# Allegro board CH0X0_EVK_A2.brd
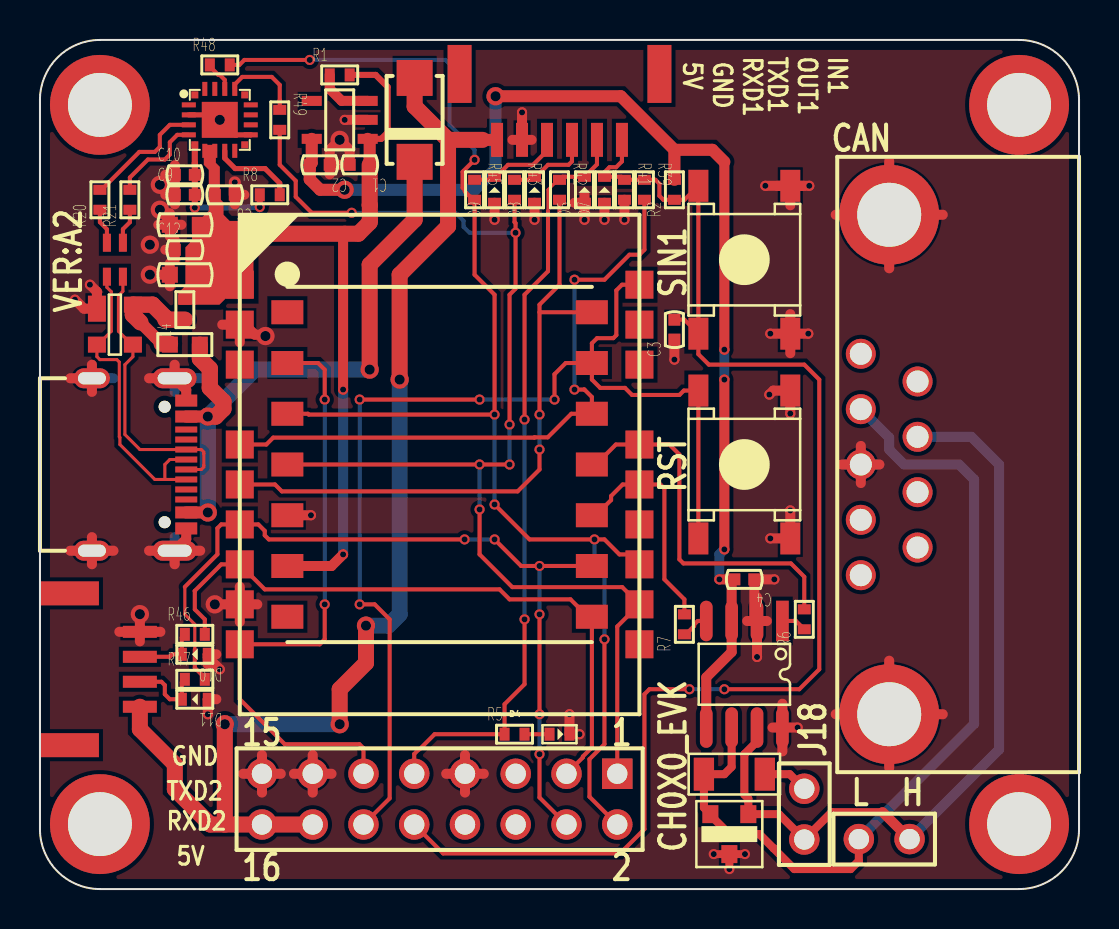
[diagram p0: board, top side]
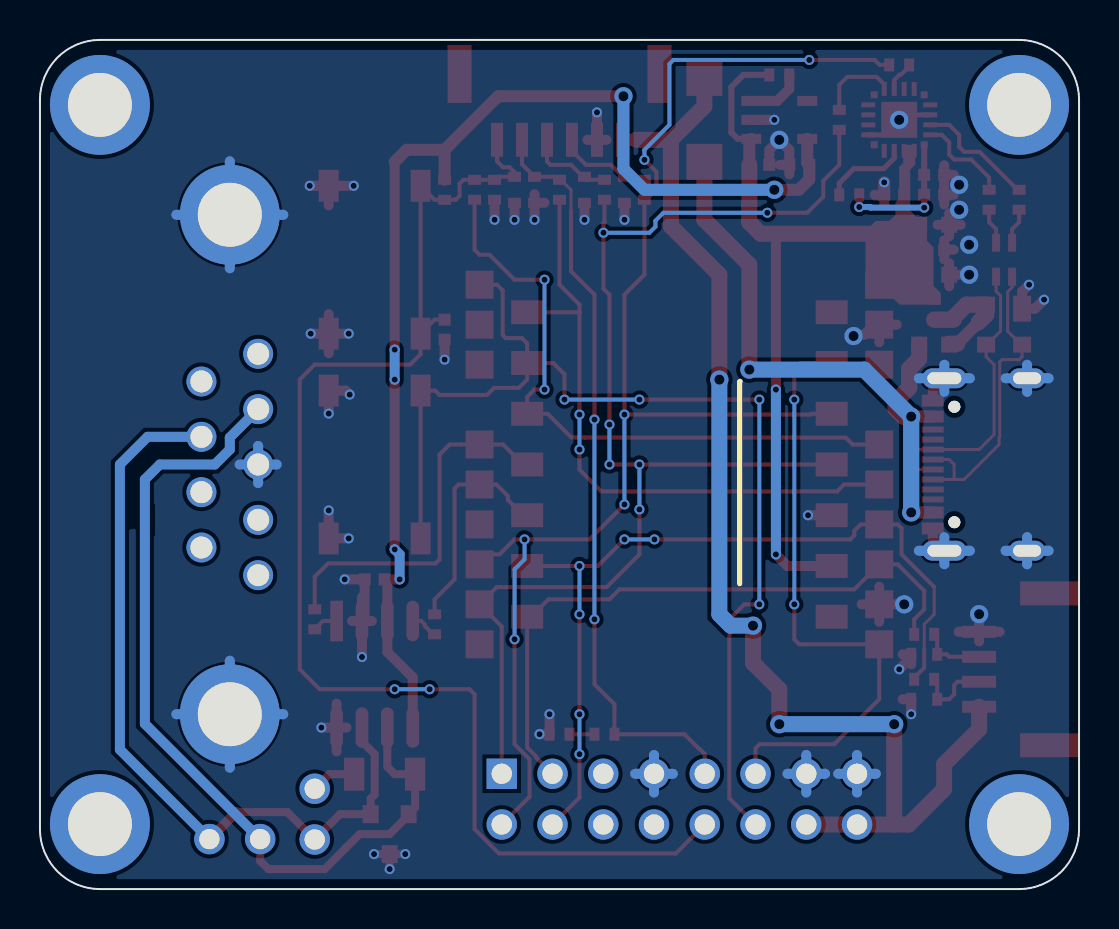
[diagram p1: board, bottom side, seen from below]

Outline 52 x 42.5 mm; copper layers: TOP, BOTTOM. Coordinates in mm from the lower left corner of the outline.
Outline path: 0,39.5 0,3 arc(0.88,0.88) 3,0 49,0 arc(51.12,0.88) 52,3 52,39.5 arc(51.12,41.62) 49,42.5 3,42.5 arc(0.88,41.62) 0,39.5

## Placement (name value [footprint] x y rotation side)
C1  0.1uF  [C0402]  16 36.25 180 top
C2  1uF  [C0402]  14 36.25 180 top
C3  0.1uF  [C0402]  31.75 28 90 top
C4  0.1uF  [C0402]  35.25 15.5 180 top
C7  10uF  [C0603]  7.25 33.25 0 top
C8  0.1uF  [C0402]  9.25 34.75 180 top
C9  0.1uF  [C0402]  7.25 34.75 0 top
C10  1uF  [C0402]  7.25 35.75 0 top
C11  10uF  [C0603]  7.25 30.75 0 top
C12  0.1uF  [C0402]  7.25 32 0 top
D1  1N4007  [DO-214AC]  18.75 38.5 90 top
D3  SM24CANB-02HTG  [SOT23-3-0_95]  34.5 2.75 180 top
D4  RED  [LED0402]  26 7.75 0 top
D6  SBD52C05L01  [SOD-523]  27.25 35 90 top
D7  SBD52C05L01  [SOD-523]  28.25 35 90 top
D8  SBD52C05L01  [SOD-523]  24.75 35 90 top
D9  SBD52C05L01  [SOD-523]  22.75 35 90 top
D10  SBD52C05L01  [SOD-523]  7.75 11.75 180 top
D11  SBD52C05L01  [SOD-523]  7.75 9.5 180 top
DN1  UET14A05L03  [SOT143]  3.75 28.25 270 top
F2  300mA  [F0603]  7.25 27.25 180 top
H1  HOLE  [HOLE-3-MM]  3 39.25 0 top
H2  HOLE  [HOLE-3-MM]  3 3.25 0 top
H3  HOLE  [HOLE-3-MM]  49 3.25 0 top
H4  HOLE  [HOLE-3-MM]  49 39.25 0 top
J1  CON6  [A1257WV-S-6P]  26 37.5 0 top
J2  CON4  [GH1X4-1_25MM_90]  5 11 90 top
J3  CONN PCB 8x2  [HEADER2X8-2_54MM]  20 4.5 180 top
J5  DB9  [DB9_FEMALE]  42.5 21.25 270 top
J6  CONN PCB 2  [HEADER1X2-2_54MM]  42.25 2.5 180 top
J7  TYPEC-311SDS-ACP16  [TYPE_C_U262_161N]  0 21.25 270 top
J18  CON2  [HEADER1X2-2_54MM]  38.25 3.75 90 top
K1  Button2  [BUTTON_6X6]  35.25 21.25 0 top
K2  Button2  [BUTTON_6X6]  35.25 31.5 0 top
L4  FB  [L0402]  7.25 29 90 top
NOREF  -  []  51.17 41.57 0 top
NOREF#2  -  []  52 3 90 top
NOREF#3  -  []  3 42.5 0 top
R1  4.7K  [R0402]  15 40.75 0 top
R2  4.7K  [R0402]  31.75 35 90 top
R3  120R  [R1206]  34.75 5.75 180 top
R5  510R  [R0402]  23.75 7.75 0 top
R6  1K  [R0402]  38.25 13.5 90 top
R7  1K  [R0402]  32.25 13.25 90 top
R8  1K  [R0402]  11.5 34.75 0 top
R20  10R  [R0402]  3 34.5 90 top
R21  10R  [R0402]  4.5 34.5 90 top
R39  120R  [R0402]  30.25 35 270 top
R41  10K  [R0402]  29.25 35 270 top
R42  120R  [R0402]  26 35 270 top
R43  120R  [R0402]  23.75 35 270 top
R45  120R  [R0402]  21.75 35 270 top
R46  120R  [R0402]  7.75 12.75 0 top
R47  120R  [R0402]  7.75 10.5 0 top
R48  1K  [R0402]  9 41.25 0 top
R49  1K  [R0402]  12 38.5 270 top
T1  YLM2012-900T  [SMD2012_4P]  3.75 31.5 90 top
U1  RS3219-3.3YF5  [SOT23-5-0_95]  15 38.5 90 top
U2  SIT65HVD234DR  [SOP8]  35.25 10.75 270 top
U3  CH040  [CH100_MINI]  20 21.25 0 top
U4  CH020  [CH010]  20 21.25 0 top
U10  CP2012N  [QFN-20-3X3-P0_5-CP2102N]  9 38.5 0 top

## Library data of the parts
C1-C4 C7-C12 = Capacity_Nonpolarity
D1 = diode
D3 = BAT54A/SOT
D4 = LED
D6-D11 = DIODE BI-DIR TRIG
DN1 = DS_T_CA_1
F2 = Fuse
H1-H4 = HOLE
J1 = CON6
J2 = CON4
J3 = CONN PCB 8x2
J5 = CONN_DB9M_MTGTABS
J6 = CONN PCB 2
J7 = TYPE C 12P
J18 = CON2
K1 K2 = Button2
L4 = FB
R1-R3 R5-R8 R20 R21 R39 R41-R43 R45-R49 = Res
T1 = TRNSFMR 67125450
U1 = XC6210
U2 = SN65HVD234-Q1
U3 = CH100
U4 = CH020
U10 = CP2102N-A02-GQFN20

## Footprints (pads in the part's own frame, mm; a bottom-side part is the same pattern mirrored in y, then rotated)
A1257WV-S-6P
  rect 1.2x2.9 smd: (-5,3.3) (5,3.3)
  rect 0.6x1.7 smd: 1(-3.125,0) 2(-1.875,0) 3(-0.625,0) 4(0.625,0) 5(1.875,0) 6(3.125,0)
BUTTON_6X6
  rect 1x1.6 smd: 1(2.3,3.7) 2(2.3,-3.7) 3(-2.3,-3.7) 4(-2.3,3.7)
C0402
  rect 0.6x0.6 smd: 1(-0.5,0) 2(0.5,0)
C0603
  rect 0.8x0.8 smd: 1(-0.75,0) 2(0.75,0)
CH010
  rect 1.6x1.2 smd: 1(-7.62,7.62) 2(-7.62,5.08) 3(-7.62,2.54) 4(-7.62,0) 5(-7.62,-2.54) 6(-7.62,-5.08) 7(-7.62,-7.62) 8(7.62,-7.62) 9(7.62,-5.08) 10(7.62,-2.54) 11(7.62,0) 12(7.62,2.54) 13(7.62,5.08) 14(7.62,7.62)
CH100_MINI
  rect 1.4x1.4 smd: 1(-10,9) 2(-10,7) 3(-10,5) 4(-10,1) 5(-10,-1) 6(-10,-3) 7(-10,-5) 8(-10,-7) 9(-10,-9) 10(10,-9) 11(10,-7) 12(10,-5) 13(10,-3) 14(10,-1) 15(10,1) 16(10,5) 17(10,7) 18(10,9)
DB9_FEMALE
  round 1.5 hole 1.1: 1(-5.54,-1.42) 2(-2.77,-1.42) 3(0,-1.42) 4(2.77,-1.42) 5(5.54,-1.42) 6(-4.155,1.42) 7(-1.385,1.42) 8(1.385,1.42) 9(4.155,1.42)
  round 5 hole 3.2: M1(12.5,0) M2(-12.5,0)
DO-214AC
  rect 1.8x1.8 smd: 1(2.1,0) 2(-2.1,0)
F0603
  rect 0.8x0.8 smd: 1(-0.75,0) 2(0.75,0)
GH1X4-1_25MM_90
  rect 1.2x2.9 smd: (-3.8,3.5) (3.8,3.5)
  rect 0.6x1.7 smd: 1(-1.875,0) 2(-0.625,0) 3(0.625,0) 4(1.875,0)
HEADER1X2-2_54MM
  round 1.524 hole 1.016: 1(-1.27,0) 2(1.27,0)
HEADER2X8-2_54MM
  rect 1.524x1.524 hole 1.016: 1(-8.89,-1.27)
  round 1.524 hole 1.016: 2(-8.89,1.27) 3(-6.35,-1.27) 4(-6.35,1.27) 5(-3.81,-1.27) 6(-3.81,1.27) 7(-1.27,-1.27) 8(-1.27,1.27) 9(1.27,-1.27) 10(1.27,1.27) 11(3.81,-1.27) 12(3.81,1.27) 13(6.35,-1.27) 14(6.35,1.27) 15(8.89,-1.27) 16(8.89,1.27)
HOLE-3-MM
  round 5 hole 3.2: 1(0,0)
L0402
  rect 0.5x0.65 smd: 1(-0.5,0) 2(0.5,0)
LED0402
  rect 0.5x0.65 smd: 1(-0.5,0) 2(0.5,0)
QFN-20-3X3-P0_5-CP2102N
  rect 0.35x0.35 smd: 1(-1.25,1.25) 6(-1.25,-1.25) 11(1.25,-1.25) 16(1.25,1.25)
  rect 0.7x0.25 smd: 2(-1.55,0.75) 3(-1.55,0.25) 4(-1.55,-0.25) 5(-1.55,-0.75) 12(1.55,-0.75) 13(1.55,-0.25) 14(1.55,0.25) 15(1.55,0.75)
  rect 0.25x0.7 smd: 7(-0.75,-1.55) 8(-0.25,-1.55) 9(0.25,-1.55) 10(0.75,-1.55) 17(0.75,1.55) 18(0.25,1.55) 19(-0.25,1.55) 20(-0.75,1.55)
  rect 1.8x1.8 smd: 21(0,0)
R0402
  rect 0.5x0.65 smd: 1(-0.5,0) 2(0.5,0)
R1206
  rect 1.016x1.651 smd: 1(-1.524,0) 2(1.524,0)
SMD2012_4P
  rect 0.9x0.4 smd: 1(-0.85,0.4) 2(0.85,0.4) 3(-0.85,-0.4) 4(0.85,-0.4)
SOD-523
  rect 0.5x0.65 smd: 1(-0.65,0) 2(0.65,0)
SOP8
  rect 2.032x0.635 smd: 1(-2.667,1.905)
  oval 2.032x0.635 smd: 2(-2.667,0.635) 3(-2.667,-0.635) 4(-2.667,-1.905) 5(2.667,-1.905) 6(2.667,-0.635) 7(2.667,0.635) 8(2.667,1.905)
SOT23-3-0_95
  rect 0.8x0.9 smd: 1(-0.95,-1) 2(0.95,-1) 3(0,1)
SOT23-5-0_95
  rect 0.5x1 smd: 1(-0.95,-1.4) 2(0,-1.4) 3(0.95,-1.4) 4(0.95,1.4) 5(-0.95,1.4)
SOT143
  rect 1.3x0.9 smd: 1(-0.8,-0.9)
  rect 0.8x0.9 smd: 2(1,-0.9) 3(1,0.9) 4(-1,0.9)
TYPE_C_U262_161N
  round 0.6 hole 0.6 unplated: (-2.89,6.24) (2.89,6.24)
  oval 1x1.8 hole 0.6x1.4: 13(4.315,2.6) 16(-4.315,2.6)
  oval 1x2.2 hole 0.6x1.7: 14(-4.315,6.74) 15(4.315,6.74)
  rect 0.6x1.1 smd: A1B12(-3.2,7.32) A4B9(-2.4,7.32) B1A12(3.2,7.32) B4A9(2.4,7.32)
  rect 0.3x1.1 smd: A5(-1.25,7.32) A6(-0.25,7.32) A7(0.25,7.32) A8(1.25,7.32) B5(1.75,7.32) B6(0.75,7.32) B7(-0.75,7.32) B8(-1.75,7.32)

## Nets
GND: C1.2 C2.1 C3.1 C4.1 C7.1 C8.1 C9.1 C10.1 C11.1 C12.1 D3.3 D4.2(-) D6.1 D7.1 D8.1 D9.1 D10.1 D11.1 DN1.1 J1.2 J2.4 J3.7(12) J3.13(15) J3.15(16) J5.3 J5.M1 J5.M2 J7.13(S1) J7.14(S2) J7.15(S3) J7.16(S4) J7.A1B12(GND#A1B12) J7.B1A12(GND#B1A12) K1.1 K1.2 K2.1 K2.2 R41.2 U1.2(VSS) U2.2(GND) U2.8(RS) U3.2(GND#2) U3.8(GND#8) U4.5(GND) U10.3(GND#3) U10.12(GND#12) U10.21(GND#21)
VBUS: D1.2(N) F2.1 J7.A4B9(VBUS#A4B9) J7.B4A9(VBUS#B4A9)
VCC: DN1.4 F2.2 L4.1
CAN_RX: R7.2 U3.14(CAN_RX) U4.10(CAN_RX)
CAN_TX: R6.2 U3.15(CAN_TX) U4.11(CAN_TX)
CANH: D3.1 J5.7 J6.1 J18.1 U2.7(CAN-H)
CANL: D3.2 J5.2 J6.2 R3.2 U2.6(CAN-L)
CC2: J7.B5(CC2)
CP2104_RXD: R49.1 U10.17(RXD)
CP2104_TXD: R48.1 U10.18(TXD)
DP3V3: C2.2 C4.2 R2.2 U1.5(VOUT) U2.3(VCC) U2.5(EN)
DP5V: C1.1 C7.2 C8.2 C11.2 C12.2 L4.2 R1.2 U1.1(VIN) U3.1(VCC) U4.6(VCC) U10.7(VREGIN) U10.8(VBUS)
EN: U3.3(EN)
IO5: J3.11(14) U3.9(IO5) U4.2(IO5)
NRST: J3.12(6) K1.3 K1.4 U3.18(NRST) U4.13(NRST)
POWER: D1.1(P) J1.1 J2.1 J3.14(7) J3.16(8)
RXD1: J3.2(1) R45.2 R48.2 U3.12(RXD1) U4.3(RXD1)
RXD2: J3.4(2) R47.2 U3.6(RXD2) U4.9(RXD2)
RXD_1: D9.2 J1.3 R45.1
RXD_2: D11.2 J2.2 R47.1
SIN: C3.2 D7.2 J1.6 J3.10(5) K2.3 K2.4 R2.1 R39.1 R41.1
SOUT: D6.2 J1.5 J3.9(13) R5.1 R42.1
SYNC_IN: R39.2 U3.4(SYNC_IN) U4.12(SYNC_IN)
SYNC_OUT: R42.2 U3.5(SYNC_OUT) U4.14(SYNC_OUT)
TXD1: J3.1(9) R43.2 R49.2 U3.11(TXD1) U4.4(TXD1)
TXD2: J3.3(10) R46.2 U3.7(TXD2) U4.8(TXD2)
TXD_1: D8.2 J1.4 R43.1
TXD_2: D10.2 J2.3 R46.1
USB_DN: DN1.3 J7.A7(DN1) J7.B7(DN2) T1.3(OUT1)
USB_DP: DN1.2 J7.A6(DP1) J7.B6(DP2) T1.1(IN1)
N1746824: D4.1(+) R5.2
N1748528: R1.1 U1.3(CE)
N1750382: R7.1 U2.4(RXD)
N1750594: R6.1 U2.1(TXD)
N1756014: C9.2 C10.2 R8.1 U10.6(VDD)
N1756148: R8.2 U10.9(RSTB)
N1756188: R20.1 T1.2(IN2)
N1756192: R21.1 T1.4(OUT2)
N1756238: R21.2 U10.5(D-)
N1756242: R20.2 U10.4(D+)
N1912221: J18.2 R3.1

Pads without a net: H1 1; H2 1; H3 1; H4 1; J3 5 6 8; J5 1 4 5 6 8 9; J7 A5 A8 B8; U1 4; U3 10 13 16 17; U4 1 7; U10 1 2 10 11 13 14 15 16 19 20

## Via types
v1: diameter 0.914, hole 0.508, TOP to BOTTOM, 18 vias
v2: diameter 0.508, hole 0.305, TOP to BOTTOM, 70 vias

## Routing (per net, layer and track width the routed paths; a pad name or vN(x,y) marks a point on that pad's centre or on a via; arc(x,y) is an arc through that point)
GND: length 174.3
  TOP w0.254: U10.3 8.75,38.75 v1(9,38.5) 9.75,37.75 U10.12
  TOP w0.4: D3.3 v2(33.72,1.75) ; D3.3 v2(34.5,1) ; D3.3 v2(35.28,1.75)
  TOP w0.5: D11.1 v2(8.4,8.75) ; D11.1 8.83,9.5 ; D11.1 8.4,9 ; J5.M2 45.18,33.75 ; J5.M2 42.5,31.07 ; J5.M2 42.5,36.43 ; J5.M2 39.82,33.75 ; 6.5,32.67 C7.1 ; C7.1 7.08,33.25 ; C7.1 5.92,33.25 ; C7.1 6.5,33.83 ; C1.2 15.5,37 v1(15,37.5) 14.5,37 C2.1 ; 42.5,6.07 J5.M1 ; J5.M1 39.82,8.75 ; J5.M1 45.18,8.75 ; J5.M1 42.5,11.43 ; J1.2 v2(24.12,38.88) ; J1.2 23.65,37.5 ; J1.2 24.6,37.5 ; 5.46,25.56 J7.14 ; J7.14 6.74,26.24 ; J7.14 7.32,24.98 J7.A1B12 ; J3.13 13.65,6.71 ; J3.13 12.71,5.77 ; J3.13 13.65,4.83 ; J3.13 14.59,5.77 ; C10.1 6.75,36.23 ; C10.1 6.27,35.75 ; C10.1 6.75,35.27 ; D8.1 v2(24.75,33.5) ; D6.1 27.25,34.78 ; D6.1 v2(27.25,33.5) ; D6.1 26.75,34.35 ; 20.33,5.77 J3.7 ; J3.7 21.27,4.83 ; J3.7 21.27,6.71 ; J3.7 22.21,5.77 ; 1.52,25.56 J7.16 ; J7.16 2.6,24.89 ; J7.16 2.6,26.24 ; 5.46,16.93 J7.15 ; J7.15 8.02,16.93 ; J7.15 7.32,17.52 J7.B1A12 ; J7.15 6.74,16.26 ; J2.4 v1(5,13.76) ; J2.4 3.97,12.88 ; J2.4 5,12.4 ; J2.4 6.03,12.88 ; J7.13 2.6,17.61 ; J7.13 3.68,16.93 ; J7.13 2.6,16.26 ; J7.13 1.52,16.93 ; D9.1 v2(22.75,33.5) ; J3.15 12.05,5.77 ; J3.15 11.11,6.71 ; J3.15 10.17,5.77 ; J3.15 11.11,4.83 ; C12.1 6.75,32.48 ; C12.1 6.75,31.52 ; C12.1 6.27,32 ; K2.1 v2(36.3,35.2) ; K2.1 37.55,34.22 ; K2.1 38.23,35.2 ; K2.1 v2(38.5,35.2) ; K2.1 36.87,35.2 ; D10.1 8.4,11.6 v2(9,11) ; D10.1 8.4,11.25 ; D10.1 8.83,11.75 ; v2(36.75,15.5) C4.1 35.75,13.55 U2.2 ; 41.08,20.32 J5.3 ; J5.3 42.01,21.25 ; J5.3 41.08,22.18 ; J5.3 40.15,21.25 ; 10,27.37 U3.2 ; U3.2 9.12,28.25 ; U3.2 10.25,28.25 10.75,27.75 11.21,27.75 v1(11.28,27.68) ; U2.2 36.38,13.42 ; U2.2 v2(35.88,11.61) ; U2.2 35.88,14.61 ; U2.2 35.39,13.42 ; U2.8 v2(37.92,8.08) ; U2.8 37.15,6.89 ; U2.8 36.66,8.08 ; U2.8 37.15,9.28 ; v2(37.55,23.8) K1.1 36.7,24.95 v2(36.5,24.75) ; 10.23,34.75 C8.1 9.75,34.27 ; 6.75,34.27 C9.1 ; C9.1 6.27,34.75 ; C9.1 6.75,35.23 ; U3.8 10,15.13 ; U3.8 v1(8.75,14.25) ; U3.8 10.88,14.25 ; U3.8 10,13.37 ; K2.2 37.55,28.78 ; K2.2 v2(36.55,27.8) ; K2.2 37.55,26.82 ; K2.2 v2(38.45,27.8) ; v2(27,7.75) D4.2 v2(26.5,8.75) ; v2(36.55,17.55) K1.2 v2(37.55,18.95) ; C2.1 14.5,35.77 ; C2.1 14.98,36.25 ; U4.5 v2(13.56,18.71) ; 5.92,30.75 C11.1 ; C11.1 6.5,30.17 ; C11.1 6.5,31.33 ; U1.2 v2(15.25,38.5) ; R41.2 v2(29.25,33.5) ; C3.1 v2(31.75,26.5) ; v2(1.75,29.5) 2.2,29.05 DN1.1 2.85,29.9 v2(2.5,30.25) ; D7.1 v2(28.25,33.5)
  TOP w0.6: C8.1 v2(9.75,35.37)
  BOTTOM w0.5: J3.15 12.05,5.77 ; J3.15 10.17,5.77 ; J3.15 11.11,6.71 ; J3.15 11.11,4.83 ; J5.M1 42.5,11.43 ; J5.M1 45.18,8.75 ; J5.M1 39.82,8.75 ; J5.M1 42.5,6.07 ; J5.M2 42.5,36.43 ; J5.M2 45.18,33.75 ; J5.M2 39.82,33.75 ; J5.M2 42.5,31.07 ; J7.16 3.68,25.56 ; J7.16 2.6,26.24 ; J7.16 1.52,25.56 ; J7.16 2.6,24.89 ; J3.7 21.27,6.71 ; J3.7 20.33,5.77 ; J3.7 21.27,4.83 ; J3.7 22.21,5.77 ; J7.15 6.74,17.61 ; J7.15 6.74,16.26 ; J7.15 8.02,16.93 ; J7.15 5.46,16.93 ; J7.14 6.74,26.24 ; J7.14 5.46,25.56 ; J7.14 6.74,24.89 ; J7.14 8.02,25.56 ; 12.71,5.77 J3.13 ; J3.13 14.59,5.77 ; J3.13 13.65,6.71 ; J3.13 13.65,4.83 ; 1.52,16.93 J7.13 ; J7.13 3.68,16.93 ; J7.13 2.6,16.26 ; J7.13 2.6,17.61 ; J5.3 42.01,21.25 ; J5.3 40.15,21.25 ; J5.3 41.08,20.32 ; J5.3 41.08,22.18
  vias: v1(5.5,32.25) v1(5.5,30.75) v1(6,35.25) v1(6,34)
VBUS: length 32
  TOP w0.6: 8,26.55 8,26.54 ; J7.A4B9 v1(8.4,23.65) ; J7.B4A9 v1(8.4,18.85)
  TOP w0.8: D1.2 18.75,33.5 16.5,31.25 v1(16.5,26) ; F2.1 8,26.55
  TOP w0.813: 8,26.54 8.5,26.05 8.5,25.08 9.18,24.41 9.18,24.04 8.79,23.65 v1(8.4,23.65)
  BOTTOM w0.8: v1(16.5,26) 10.75,26 v1(8.4,23.65)
  BOTTOM w0.813: v1(8.4,18.85) v1(8.4,23.65)
VCC: length 6.5
  TOP w0.6: F2.2 6.14,27.25 5.75,27.64 5.02,28.37 ; 6.28,28.5 6.38,28.5
  TOP w0.813: 5.02,28.37 4.65,28.74 DN1.4 5.63,29.25 6.28,28.61 ; 6.28,28.61 6.38,28.5 L4.1 ; 6.28,28.61 6.28,28.5 ; 6.5,27.3 6.09,27.3
CAN_RX: length 11.2
  TOP w0.203: R7.2 32.25,14.5 31.25,15.5 31.25,20.05 31.05,20.25 U3.14 29.16,20.25 28.58,19.67 28.58,19.47 27.82,18.71 U4.10
CAN_TX: length 18.5
  TOP w0.203: U4.11 27.82,21.25 28.82,22.25 U3.15 30.93,22.25 31.5,22.25 32,21.75 32,16.5 32.2,16.3 37.58,16.3 38.25,15.63 R6.2
CANH: length 39.7
  TOP w0.4: U2.7 35.88,7.38 35.25,6.75 35.25,4.73 35.45,4.53 D3.1 36.98,3.75 J18.1 39.62,3.85 42.17,3.85
  TOP w0.5: 42.17,3.85 J6.1
  BOTTOM w0.5: J6.1 48,6.98 48,21.25 46.61,22.64 J5.7
CANL: length 43.4
  TOP w0.4: J6.2 40.98,1.41 40.57,1 37.75,1 36.71,2.04 36.71,2.04 36,2.75 34.5,2.75 33.55,3.7 D3.2 33.23,4.07 R3.2 34.25,5.75 34.61,6.11 U2.6
  BOTTOM w0.5: J5.2 42.5,22.6 42.5,22 43.25,21.25 46,21.25 46.75,20.5 46.75,8.27 J6.2
CP2104_RXD: length 4
  TOP w0.203: R49.1 12,39.48 12,40.25 11.6,40.65 10.12,40.65 9.75,40.28 U10.17
CP2104_TXD: length 1.6
  TOP w0.203: R48.1 8.5,41.18 8.91,40.76 8.99,40.76 9.25,40.5 U10.18
DP3V3: length 60.4
  TOP w0.305: U2.5 33.34,7.38
  TOP w0.5: U2.5 33.34,10.6 34.61,11.87 U2.3 34.61,15.36 C4.2 v2(34,15.5) ; v2(34.25,27) 34.25,36.4 ; v2(34.25,17) v2(34.25,25.5)
  TOP w0.6: 31.75,37 29.07,39.68 v1(22.8,39.68) ; 31.75,37 R2.2 ; 31.75,37 33.65,37 34.25,36.4 ; v1(15.25,35) 14.02,35 13.5,35.52 C2.2 13.6,36.35 U1.5
  BOTTOM w0.5: v2(34,15.5) 34,16.75 v2(34.25,17) ; v2(34.25,25.5) v2(34.25,27)
  BOTTOM w0.6: v1(15.25,35) 21.75,35 22.8,36.05 v1(22.8,39.68)
DP5V: length 35.8
  TOP w0.305: U1.1 17.08,37.55 17.4,37.87 17.4,40.15 16.8,40.75 R1.2
  TOP w0.5: 15.25,32.8 15.17,32.72 v2(15.17,25) ; U4.6 14.59,16.17 v2(15.17,16.75)
  TOP w0.6: C1.1 16.5,37.45 U1.1
  TOP w0.8: 9.85,32.8 15.93,32.8 16.5,33.37 16.5,33.47 16.51,33.47 16.51,34.23 16.5,34.23 C1.1
  BOTTOM w0.5: v2(15.17,16.75) v2(15.17,25)
IO5: length 31.1
  TOP w0.203: v2(14.25,24.5) 14.25,26 13.92,26.33 U4.2 ; J3.11 16.19,7.05 15.99,7.25 12.25,7.25 10,9.5 U3.9 14,12.25 14.25,12.5 v2(14.25,14.25)
  BOTTOM w0.203: v2(14.25,14.25) v2(14.25,24.5)
NRST: length 55.9
  TOP w0.203: v2(22,24.5) v2(16,24.5) ; K1.3 K1.4 32.22,24.95 32,24.73 29.63,24.73 29.28,25.09 28.04,25.09 27.62,25.5 U4.13 ; U4.13 27.62,27.32 27.88,27.57 28.69,27.57 28.84,27.73 28.84,29.96 29.13,30.25 U3.18 ; U4.13 26.31,26.33 25.75,25.77 v2(25.75,24.5) ; J3.12 17.5,4.54 17.5,13.5 16.75,14.25 v2(16,14.25)
  BOTTOM w0.203: v2(25.75,24.5) v2(22,24.5) ; v2(16,24.5) v2(16,14.25)
POWER: length 61.6
  TOP w0.6: 22.15,37.5 J1.1
  TOP w0.8: J3.14 J3.16 9.25,3.23 ; v1(9.25,8.25) 9.25,3.23 ; 9.25,3.23 8.52,3.23 6.75,5 6.75,6.25 5,8 J2.1 ; D1.1 18.75,39.17 20.42,37.5 ; 20.42,37.5 22.15,37.5 ; 20.42,37.5 20.42,33.17 18,30.75 v1(18,25.5) ; v1(15,8.25) 15,10 16.32,11.32 v1(16.32,13.18)
  BOTTOM w0.8: v1(16.32,13.18) 17.43,13.18 18,13.75 v1(18,25.5) ; v1(9.25,8.25) v1(15,8.25)
RXD1: length 69
  TOP w0.203: R48.2 9.98,41.25 10.23,41.5 v2(13.5,41.5) ; U4.3 13.41,23.79 13.45,23.75 v2(22.75,23.75) 22.75,29.75 21.75,30.75 R45.2 21.67,34.5 21.26,34.91 21.26,34.99 21.15,35.1 21.15,35.9 v2(21.75,36.5) ; J3.2 27.5,4.62 27.5,6.5 28.25,7.25 v2(28.25,12.5) ; v2(22.75,19.25) 24.5,17.5 v2(27.75,17.5) 28.25,17.5 29,16.75 29.5,16.75 U3.12
  BOTTOM w0.203: v2(27.75,17.5) 27.75,16.5 28.25,16 v2(28.25,12.5) ; v2(22.75,19.25) v2(22.75,23.75) ; v2(13.5,41.5) 20.3,41.5 20.5,41.3 20.5,38.25 21.75,37 v2(21.75,36.5)
RXD2: length 42
  TOP w0.152: 7.75,12 7.75,13.25 7.25,13.75 7.25,15.12
  TOP w0.203: 7.75,12 7.75,11.07 8.25,10.57 R47.2 ; U4.9 v2(25,16.17) 24.08,16.17 v2(22.75,17.5) ; 7.25,15.12 8.88,16.75 8.88,18.06 9.07,18.25 U3.6 10.93,18.25 11.25,17.93 11.25,17.7 11.45,17.5 v2(21.25,17.5) ; v2(25,8.75) v2(25,13.75) ; J3.4 25,4.58 v2(25,6.75)
  BOTTOM w0.203: v2(21.25,17.5) v2(22.75,17.5) ; v2(25,13.75) v2(25,16.17) ; v2(25,6.75) v2(25,8.75)
RXD_1: length 4.8
  TOP w0.203: R45.1 22.6,35.5 D9.2 22.82,35.65 23.42,36.25 24.68,36.25 25.38,36.95 J1.3
RXD_2: length 3.8
  TOP w0.203: J2.2 5,10.37 6.08,10.37 6.25,10.2 6.25,9.75 6.5,9.5 D11.2 7.1,10.35 R47.1
SIN: length 67.9
  TOP w0.203: J1.6 29.12,36.42 28.83,36.13 28.5,36.13 28.25,35.88 D7.2 29.1,35.65 R41.1 R39.1 30.8,35.5 31,35.3 31,34.7 31.2,34.5 R2.1 32.25,34.5 K2.4 K2.3 ; C3.2 32.25,28.5 K2.3 ; K2.3 32.95,26.77 33.47,26.25 38.25,26.25 39,25.5 39,11 38,10 v2(34.25,10) ; J3.10 20.18,1.78 29.03,1.78 30.25,3 30.25,9.75 30.5,10 v2(32.5,10)
  BOTTOM w0.203: v2(34.25,10) v2(32.5,10)
SOUT: length 38.3
  TOP w0.152: 25.42,33.94 25.42,35 25.92,35.5 R42.1
  TOP w0.203: R42.1 26.15,35.65 D6.2 27.88,36.28 J1.5 ; v2(24.25,13.5) 24.25,10.25 23.25,9.25 R5.1 19.75,7.75 19,7 18.97,7 18.73,6.76 J3.9 ; v2(24.25,23.5) 24.25,29.75 25.42,30.93 25.42,33.94
  BOTTOM w0.203: v2(24.25,23.5) v2(24.25,13.5)
SYNC_IN: length 32.2
  TOP w0.203: v2(26.75,30.5) 28.25,30.5 29.5,31.75 30,31.75 30.25,32 R39.2 ; U3.4 11.33,22.25 11.67,22.6 24.73,22.6 24.75,22.61 25.41,22.61 26.59,23.79 U4.12 27.62,24.63 27.25,25 27.23,25 v2(26.75,25)
  BOTTOM w0.203: v2(26.75,30.5) v2(26.75,25)
SYNC_OUT: length 32.1
  TOP w0.203: v2(25,23.75) 25,28.87 ; 25,28.87 25,29.25 26,30.25 R42.2 ; 25,28.87 U4.14 ; U3.5 11.76,20.25 12.11,19.9 23.9,19.9 25,21 v2(25,22)
  BOTTOM w0.203: v2(25,22) v2(25,23.75)
TXD1: length 62.6
  TOP w0.203: v2(22,19) 22,16.75 23.64,15.11 29.14,15.11 U3.11 28.89,13.14 J3.1 ; R49.2 12,36.25 12.8,35.45 12.8,34.65 13.6,33.85 v2(15.6,33.85) ; v2(23.5,21.25) v2(22,21.25) U4.4 ; R43.2 23.75,33.38 23.8,33.33 v2(23.8,32.85) 23.8,30.05 23.5,29.75 v2(23.5,23.25)
  BOTTOM w0.203: v2(23.8,32.85) 21.5,32.85 21.2,33.15 21.2,33.45 20.8,33.85 v2(15.6,33.85) ; v2(22,19) v2(22,21.25) ; v2(23.5,23.25) v2(23.5,21.25)
TXD2: length 32.3
  TOP w0.203: R46.2 8.25,13.5 7.75,14 7.75,14.92 7.74,14.92 9.07,16.25 U3.7 11.25,15 23,15 23.5,14.5 26.55,14.5 27.42,13.63 U4.8 27.62,7.09 27.17,6.64 27.17,6.59 J3.3
TXD_1: length 4.3
  TOP w0.203: R43.1 24.6,35.5 D8.2 24.82,35.65 25.42,36.25 26.45,36.25 26.62,36.42 J1.4
TXD_2: length 3.2
  TOP w0.203: J2.3 6.5,11.62 6.62,11.75 D10.2 7.1,12.6 R46.1
USB_DN: length 14.5
  TOP w0.152: J7.A7 8.07,21 8.2,21.13 8.2,21.21 8.2,21.21 8.2,21.79 8.2,21.79 8.2,21.87 8.07,22 J7.B7 5,22 4.25,22.75 4.25,26.25 4.65,26.65 DN1.3 4.6,27.25 3.93,27.92 3.93,29.7 4.15,29.92 T1.3
USB_DP: length 15.8
  TOP w0.152: 6.25,20.5 5.75,20.5 4,22.25 4,22.6 3.97,22.63 3.97,26.38 3.85,26.5 3,26.5 2.85,26.65 DN1.2 2.9,27.25 3.57,27.92 3.57,29.9 3.35,30.12 T1.1 ; 6.25,20.5 6.25,21.25 6.5,21.5 J7.A6 ; 6.25,20.5 J7.B6
N1746824: length 1.3
  TOP w0.203: R5.2 D4.1
N1748528: length 2.8
  TOP w0.5: R1.1 14.5,40.05 15.1,39.45 U1.3
N1750382: length 1.4
  TOP w0.203: R7.1 32.33,12.75 32.74,13.16 32.74,13.24 32.92,13.42 U2.4
N1750594: length 1.3
  TOP w0.203: U2.1 37.83,13.42 R6.1
N1756014: length 7
  TOP w0.305: v2(7.75,34.11) 7.75,34.75 C9.2 C10.2 7.75,36.33 U10.6 ; R8.1 v2(11,34.14)
  BOTTOM w0.305: v2(11,34.14) 10.47,34.14 10.44,34.11 v2(7.75,34.11)
N1756148: length 4.2
  TOP w0.254: R8.2 12,35.33 11.27,36.06 9.77,36.06 9.25,36.58 U10.9
N1756188: length 1.8
  TOP w0.203: R20.1 3,33.38 3.35,33.03 T1.2
N1756192: length 1.8
  TOP w0.203: T1.4 4.15,33.03 4.5,33.38 R21.1
N1756238: length 4.8
  TOP w0.203: U10.5 6.87,37.75 6.5,37.38 6.5,36.77 6.25,36.52 5.4,36.52 4.5,35.61 R21.2
N1756242: length 6.1
  TOP w0.203: R20.2 3.07,35 4.97,36.9 5.75,36.9 6,37.15 6,37.75 6.5,38.25 U10.4
N1912221: length 2.3
  TOP w0.4: R3.1 37.52,5.75 J18.2

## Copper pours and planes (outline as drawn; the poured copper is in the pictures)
GND on TOP: 3,0.5 0.5,3 0.5,39.5 3,42 49.25,42 51.5,39.75 51.5,3 49,0.5 ; 38 cut-outs
GND on BOTTOM: 3,0.5 0.5,3 0.5,39.5 3,42 49.25,42 51.5,39.75 51.5,3 49,0.5 ; 2 cut-outs
DP5V on TOP (solid shape): 8.8,36.35 9,36.15 9,34.55 9.19,34.36 9.19,33.75 9.49,33.44 10.18,33.44 10.68,32.93 10.68,29.56 9.29,29.56 8.98,29.25 6.92,29.25 6.92,29.84 7.28,30.19 7.28,32.12 7.61,32.45 7.61,33.57 8.07,33.57 8.45,33.95 8.45,36 8.2,36.25 8.2,37.25 8.8,37.25

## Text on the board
Ref Des/Silkscreen Top: TXD2 | RXD2 | GND | 5V | RXD1 | TXD1 | OUT1 | IN1 | 15 | 16 | 1 | 2 | CAN | L | H | VER:A2 | SIN1 | RST | CH0X0_EVK | J18
DEVICE_TYPE_TOP: FIGURE | SIZE | 12.0 | 20.0 | 21.654 | 40.0 | 86.61 | 141.732 | 59.055x23.622 | 70.866x23.622 | DRILL CHART: TOP to BOTTOM | ALL UNITS ARE IN MILS | PLATED | NON-PLATED | QTY | 47 | 3 | 28 | 32 | 4 | 1 | 2
